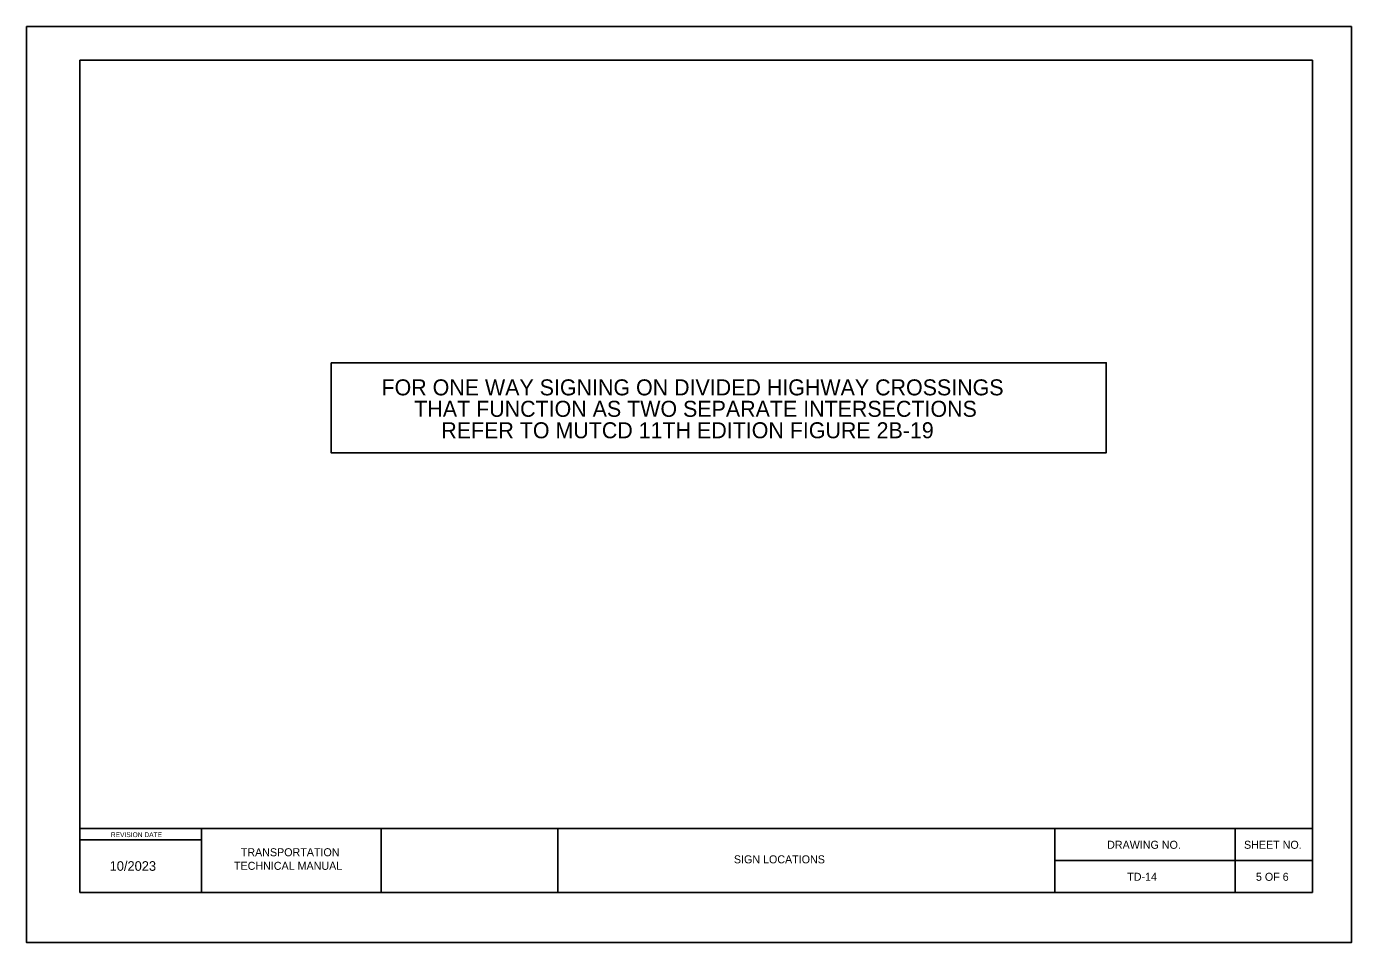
# Model space of a CAD drawing. Extents: x -14.6 to 39.7, y -12.4 to 25.1.
import ezdxf

# ---------------------------------------------------------------- set-up
doc = ezdxf.new("R2010")
doc.units = 0
for name, color, linetype in [('Default', 7, 'Continuous'), ('NonPlottingEle_dp', 7, 'Continuous'), ('SheetBorder_dp', 7, 'Continuous'), ('SheetLines_dp', 7, 'Continuous'), ('TextMinor', 7, 'Continuous')]:
    doc.layers.add(name, color=color, linetype=linetype)

msp = doc.modelspace()

# ---------------------------------------------------------------- linework, layer by layer
at = {"layer": 'Default'}
msp.add_lwpolyline([(-2.085, 11.359), (29.691, 11.359), (29.691, 7.669), (-2.085, 7.669)], close=True, dxfattribs=at)
at = {"layer": 'NonPlottingEle_dp'}
msp.add_lwpolyline([(38.12, 25.141), (-14.569, 25.141), (-14.569, -12.409), (39.74, -12.409), (39.74, 25.141)], close=True, dxfattribs=at)
at = {"layer": 'SheetBorder_dp'}
for p, q in [((-12.382, 23.76), (-12.382, -10.361)), ((-12.382, 23.76), (38.143, 23.76)), ((38.143, 23.76), (38.143, -10.361)), ((-12.382, -7.741), (38.143, -7.741)), ((-12.382, -10.361), (38.143, -10.361))]:
    msp.add_line(p, q, dxfattribs=at)
at = {"layer": 'SheetLines_dp'}
for p, q in [((-7.394, -7.736), (-7.394, -10.361)), ((-0.027, -7.736), (-0.027, -10.361)), ((7.208, -7.741), (7.208, -10.361)), ((27.582, -10.361), (27.582, -7.736)), ((34.972, -10.361), (34.972, -7.736)), ((-12.382, -8.196), (-7.394, -8.196)), ((27.582, -9.049), (38.143, -9.049))]:
    msp.add_line(p, q, dxfattribs=at)

# ---------------------------------------------------------------- texts
at = {"layer": 'TextMinor'}
for s, height, p in [('FOR ONE WAY SIGNING ON DIVIDED HIGHWAY CROSSINGS ', 0.65617, (-0.018, 10.02)), ('THAT FUNCTION AS TWO SEPARATE INTERSECTIONS ', 0.65617, (1.325, 9.141)), ('REFER TO MUTCD 11TH EDITION FIGURE 2B-19', 0.65617, (2.433, 8.261)), ('REVISION DATE', 0.19685, (-11.112, -8.089)), ('TRANSPORTATION', 0.32808, (-5.786, -8.873)), ('DRAWING NO.', 0.32808, (29.724, -8.567)), ('SHEET NO.', 0.3281, (35.335, -8.567)), ('10/2023', 0.3937, (-11.162, -9.47)), ('TECHNICAL MANUAL', 0.32808, (-6.066, -9.43)), ('SIGN LOCATIONS', 0.32808, (14.426, -9.164)), ('TD-14', 0.3281, (30.548, -9.879)), ('5 OF 6 ', 0.3281, (35.824, -9.879))]:
    msp.add_text(s, height=height, dxfattribs=at).set_placement(p)

doc.saveas('drawing.dxf')
